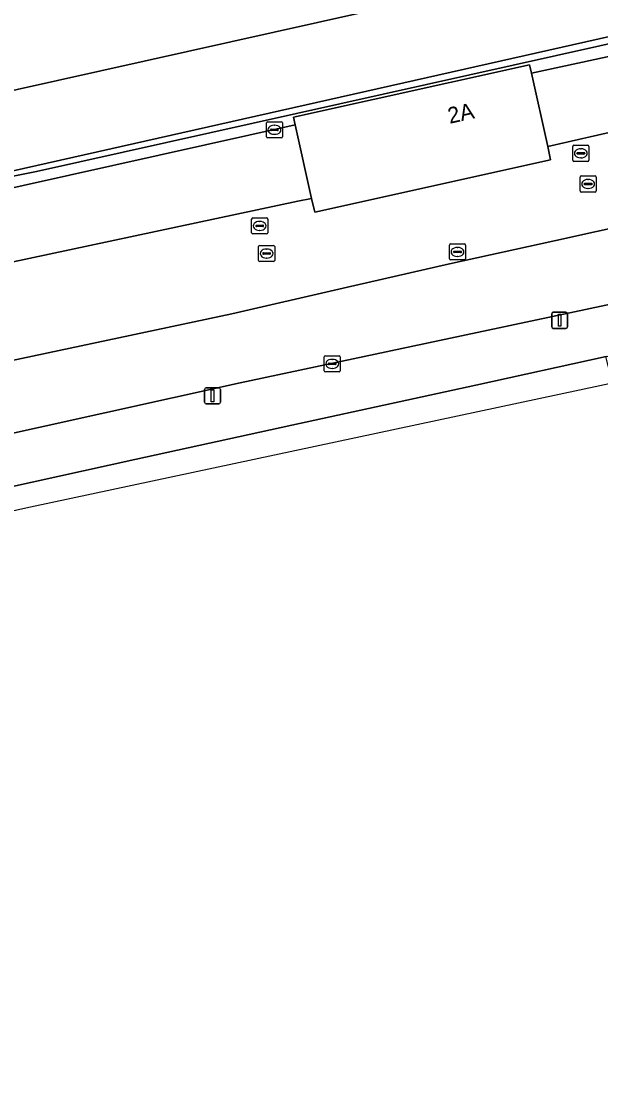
# Model space of a CAD drawing. Extents: x 160806 to 161707, y 383696 to 384148.
# Drawn here: x 161634.3 to 161670.2, y 383820.6 to 383887.5 of the extents above; entities that cross this region are included whole.
import ezdxf

# ---------------------------------------------------------------- set-up
doc = ezdxf.new("R2010")
doc.units = 0
for name, color, linetype in [('IMGEO_Grasland_overig', 7, 'Continuous'), ('IMGEO_Groenvoorziening', 7, 'Continuous'), ('IMGEO_Hek', 7, 'Continuous'), ('IMGEO_Kolk', 7, 'Continuous'), ('IMGEO_Lichtmast', 7, 'Continuous'), ('IMGEO_Pand', 7, 'Continuous'), ('IMGEO_Pand_nummerreeks', 7, 'Continuous'), ('IMGEO_Parkeervlak_open', 7, 'Continuous'), ('IMGEO_Rijbaan_lokaal_open', 7, 'Continuous'), ('IMGEO_Rioolput', 7, 'Continuous'), ('IMGEO_Spoorbaan_halfverhard', 7, 'Continuous')]:
    doc.layers.add(name, color=color, linetype=linetype)

msp = doc.modelspace()

# ---------------------------------------------------------------- linework, layer by layer
at = {"layer": 'IMGEO_Grasland_overig'}
msp.add_lwpolyline([(161630.532, 383877.228), (161635.195, 383878.161), (161675.596, 383887.152), (161680.158, 383888.167), (161679.423, 383891.492), (161674.766, 383890.452), (161675.408, 383887.573), (161606.306, 383872.021), (161606.363, 383871.769)], close=True, dxfattribs=at)
at = {"layer": 'IMGEO_Groenvoorziening'}
for points in [[(161675.596, 383887.152), (161635.195, 383878.161), (161630.532, 383877.228), (161606.363, 383871.769), (161606.519, 383871.073), (161626.185, 383875.445), (161628.76, 383876.043), (161651.274, 383881.048), (161651.168, 383881.526), (161665.845, 383884.775), (161665.96, 383884.257), (161675.376, 383886.281)], [(161521.635, 383833.723), (161580.201, 383846.689), (161582.51, 383847.687), (161585.012, 383847.75), (161614.342, 383854.325), (161641.301, 383860.274), (161651.06, 383862.411), (161662.497, 383864.892), (161670.593, 383866.669), (161682.93, 383869.376), (161687.731, 383870.454), (161692.46, 383871.911), (161696.167, 383872.737), (161692.17, 383874.476), (161678.693, 383871.571), (161647.839, 383865.039), (161626.972, 383860.422), (161609.694, 383856.527), (161595.494, 383853.326)]]:
    msp.add_lwpolyline(points, dxfattribs=at)
at = {"layer": 'IMGEO_Hek'}
for points in [[(161679.423, 383891.492), (161674.766, 383890.452), (161675.408, 383887.573), (161592.484, 383868.91)], [(161468.352, 383821.972), (161470.021, 383822.345), (161472.634, 383822.879), (161475.023, 383823.371), (161479.934, 383824.467), (161509.272, 383830.942), (161514.217, 383832.035), (161521.635, 383833.723), (161580.201, 383846.689), (161582.51, 383847.687), (161585.012, 383847.75), (161614.342, 383854.325), (161641.301, 383860.274), (161651.06, 383862.411), (161662.497, 383864.892), (161670.593, 383866.669), (161682.93, 383869.376), (161687.731, 383870.454), (161692.46, 383871.911), (161696.167, 383872.737)]]:
    msp.add_lwpolyline(points, dxfattribs=at)
at = {"layer": 'IMGEO_Kolk'}
for p, q in [((161649.554, 383881.243), (161650.406, 383881.243)), ((161649.479, 383880.317), (161649.479, 383881.169)), ((161649.738, 383880.737), (161649.738, 383880.749)), ((161650.176, 383880.7), (161649.778, 383880.7)), ((161649.781, 383880.786), (161650.179, 383880.786)), ((161649.967, 383881.023), (161649.992, 383881.023)), ((161650.222, 383880.749), (161650.222, 383880.737)), ((161650.48, 383881.169), (161650.48, 383880.317)), ((161650.406, 383880.243), (161649.554, 383880.243)), ((161649.99, 383880.463), (161649.965, 383880.463)), ((161660.86, 383872.734), (161660.86, 383873.586)), ((161660.935, 383873.66), (161661.787, 383873.66)), ((161661.348, 383873.44), (161661.373, 383873.44)), ((161661.861, 383873.586), (161661.861, 383872.734)), ((161661.787, 383872.66), (161660.935, 383872.66)), ((161661.119, 383873.154), (161661.119, 383873.166)), ((161661.557, 383873.117), (161661.159, 383873.117)), ((161661.162, 383873.203), (161661.56, 383873.203)), ((161661.371, 383872.88), (161661.346, 383872.88)), ((161661.603, 383873.166), (161661.603, 383873.154)), ((161653.073, 383865.783), (161653.073, 383866.635)), ((161653.148, 383866.709), (161654, 383866.709)), ((161654.074, 383866.635), (161654.074, 383865.783)), ((161653.332, 383866.203), (161653.332, 383866.215)), ((161653.77, 383866.166), (161653.372, 383866.166)), ((161653.375, 383866.252), (161653.773, 383866.252)), ((161653.584, 383865.929), (161653.559, 383865.929)), ((161653.561, 383866.489), (161653.586, 383866.489)), ((161653.816, 383866.215), (161653.816, 383866.203)), ((161654, 383865.709), (161653.148, 383865.709))]:
    msp.add_line(p, q, dxfattribs=at)
for points in [[(161649.554, 383881.243), (161650.406, 383881.243)], [(161649.479, 383880.317), (161649.479, 383881.169)], [(161650.48, 383881.169), (161650.48, 383880.317)], [(161650.406, 383880.243), (161649.554, 383880.243)], [(161660.86, 383872.734), (161660.86, 383873.586)], [(161660.935, 383873.66), (161661.787, 383873.66)], [(161661.861, 383873.586), (161661.861, 383872.734)], [(161661.787, 383872.66), (161660.935, 383872.66)], [(161653.073, 383865.783), (161653.073, 383866.635)], [(161653.148, 383866.709), (161654, 383866.709)], [(161654.074, 383866.635), (161654.074, 383865.783)], [(161654, 383865.709), (161653.148, 383865.709)]]:
    msp.add_lwpolyline(points, dxfattribs=at)
for centre, radius, start, end in [((161649.556, 383881.167), 0.0765, 91.55205, 178.44795), ((161649.556, 383881.167), 0.0765, 91.55205, 178.44795), ((161650.404, 383881.167), 0.0765, 1.55205, 88.44795), ((161650.404, 383881.167), 0.0765, 1.55205, 88.44795), ((161649.778, 383880.746), 0.0403, 85.87752, 175.75265), ((161649.775, 383880.736), 0.0366, 178.93798, 274.71019), ((161650.179, 383880.743), 0.043, 264.86636, 352.45326), ((161650.183, 383880.748), 0.0386, 1.73085, 96.63898), ((161649.556, 383880.319), 0.0765, 181.55205, 268.44795), ((161649.556, 383880.319), 0.0765, 181.55205, 268.44795), ((161650.404, 383880.319), 0.0765, 271.55205, 358.44795), ((161650.404, 383880.319), 0.0765, 271.55205, 358.44795), ((161660.937, 383873.584), 0.0765, 91.55205, 178.44795), ((161660.937, 383873.584), 0.0765, 91.55205, 178.44795), ((161661.785, 383873.584), 0.0765, 1.55205, 88.44795), ((161661.785, 383873.584), 0.0765, 1.55205, 88.44795), ((161660.937, 383872.736), 0.0765, 181.55205, 268.44795), ((161660.937, 383872.736), 0.0765, 181.55205, 268.44795), ((161661.159, 383873.163), 0.0403, 85.87752, 175.75265), ((161661.156, 383873.153), 0.0366, 178.93798, 274.71019), ((161661.56, 383873.16), 0.043, 264.86636, 352.45326), ((161661.564, 383873.165), 0.0386, 1.73085, 96.63898), ((161661.785, 383872.736), 0.0765, 271.55205, 358.44795), ((161661.785, 383872.736), 0.0765, 271.55205, 358.44795), ((161653.15, 383866.633), 0.0765, 91.55205, 178.44795), ((161653.15, 383866.633), 0.0765, 91.55205, 178.44795), ((161653.998, 383866.633), 0.0765, 1.55205, 88.44795), ((161653.998, 383866.633), 0.0765, 1.55205, 88.44795), ((161653.372, 383866.212), 0.0403, 85.87752, 175.75265), ((161653.369, 383866.202), 0.0366, 178.93798, 274.71019), ((161653.773, 383866.209), 0.043, 264.86636, 352.45326), ((161653.777, 383866.214), 0.0386, 1.73085, 96.63898), ((161653.15, 383865.785), 0.0765, 181.55205, 268.44795), ((161653.15, 383865.785), 0.0765, 181.55205, 268.44795), ((161653.998, 383865.785), 0.0765, 271.55205, 358.44795), ((161653.998, 383865.785), 0.0765, 271.55205, 358.44795)]:
    msp.add_arc(centre, radius, start, end, dxfattribs=at)
for centre, major_axis, ratio, start_param, end_param in [((161649.966, 383880.743), (-0.387, 0.002), 0.722429, 4.712389, 7.853982), ((161649.991, 383880.743), (-0.39, 0.002), 0.717154, 1.570796, 4.712389), ((161661.347, 383873.16), (-0.387, 0.002), 0.722429, 4.712389, 7.853982), ((161661.372, 383873.16), (-0.39, 0.002), 0.717154, 1.570796, 4.712389), ((161653.56, 383866.209), (-0.387, 0.002), 0.722429, 4.712389, 7.853982), ((161653.585, 383866.209), (-0.39, 0.002), 0.717154, 1.570796, 4.712389)]:
    msp.add_ellipse(centre, major_axis=major_axis, ratio=ratio, start_param=start_param, end_param=end_param, dxfattribs=at)
at = {"layer": 'IMGEO_Lichtmast'}
for p, q in [((161667.214, 383868.514), (161667.214, 383869.314)), ((161667.214, 383869.314), (161667.214, 383868.514)), ((161667.314, 383869.414), (161668.104, 383869.414)), ((161668.104, 383869.414), (161667.314, 383869.414)), ((161668.204, 383869.314), (161668.204, 383868.514)), ((161668.204, 383868.514), (161668.204, 383869.314)), ((161668.104, 383868.414), (161667.314, 383868.414)), ((161667.314, 383868.414), (161668.104, 383868.414)), ((161645.634, 383863.819), (161645.634, 383864.619)), ((161645.634, 383864.619), (161645.634, 383863.819)), ((161645.734, 383864.719), (161646.524, 383864.719)), ((161646.524, 383864.719), (161645.734, 383864.719)), ((161646.624, 383864.619), (161646.624, 383863.819)), ((161646.624, 383863.819), (161646.624, 383864.619)), ((161646.524, 383863.719), (161645.734, 383863.719)), ((161645.734, 383863.719), (161646.524, 383863.719))]:
    msp.add_line(p, q, dxfattribs=at)
for points in [[(161667.634, 383869.289), (161667.784, 383869.289), (161667.784, 383868.539), (161667.634, 383868.539), (161667.634, 383869.289)], [(161646.054, 383864.594), (161646.204, 383864.594), (161646.204, 383863.844), (161646.054, 383863.844), (161646.054, 383864.594)]]:
    msp.add_lwpolyline(points, dxfattribs=at)
for centre, start, end in [((161667.314, 383869.314), 90, 180), ((161667.314, 383869.314), 90, 180), ((161668.104, 383869.314), 0, 90), ((161668.104, 383869.314), 360, 90), ((161667.314, 383868.514), 180, 270), ((161667.314, 383868.514), 180, 270), ((161668.104, 383868.514), 270, 0), ((161668.104, 383868.514), 270, 0), ((161645.734, 383864.619), 90, 180), ((161645.734, 383864.619), 90, 180), ((161646.524, 383864.619), 0, 90), ((161646.524, 383864.619), 360, 90), ((161645.734, 383863.819), 180, 270), ((161645.734, 383863.819), 180, 270), ((161646.524, 383863.819), 270, 0), ((161646.524, 383863.819), 270, 0)]:
    msp.add_arc(centre, 0.1, start, end, dxfattribs=at)
at = {"layer": 'IMGEO_Pand'}
msp.add_lwpolyline([(161599.211, 383890.337), (161600.263, 383885.614), (161600.427, 383884.879), (161600.036, 383884.793), (161601.34, 383878.893), (161601.233, 383878.87), (161601.845, 383876.066), (161608.382, 383877.494), (161614.002, 383878.754), (161614.09, 383878.359), (161623.29, 383880.412), (161623.195, 383880.838), (161668.642, 383890.98)], dxfattribs=at)
msp.add_lwpolyline([(161665.96, 383884.257), (161665.845, 383884.775), (161651.168, 383881.526), (161651.274, 383881.048), (161652.29, 383876.485), (161652.481, 383875.629), (161667.151, 383878.878), (161666.967, 383879.708)], close=True, dxfattribs=at)
at = {"layer": 'IMGEO_Parkeervlak_open'}
msp.add_lwpolyline([(161675.855, 383885.976), (161675.673, 383886.219), (161675.376, 383886.281), (161665.96, 383884.257), (161666.967, 383879.708), (161671.512, 383880.738), (161674.153, 383881.35), (161676.735, 383881.898)], close=True, dxfattribs=at)
for points in [[(161651.442, 383876.303), (161652.29, 383876.485), (161651.274, 383881.048), (161628.76, 383876.043), (161626.185, 383875.445), (161606.519, 383871.073), (161591.712, 383867.718), (161592.392, 383864.683)], [(161591.531, 383863.209), (161603.52, 383865.895), (161606.493, 383866.529), (161606.594, 383866.552), (161629.63, 383871.673), (161651.442, 383876.303)], [(161678.693, 383871.571), (161678.868, 383871.878), (161678.822, 383872.229), (161677.981, 383876.124), (161676.579, 383875.892), (161672.537, 383874.994), (161667.473, 383873.86), (161660.853, 383872.411), (161654.242, 383870.901), (161647.339, 383869.306), (161629.555, 383865.552), (161607.736, 383860.676), (161592.972, 383857.432)], [(161595.494, 383853.326), (161609.694, 383856.527), (161626.972, 383860.422), (161647.839, 383865.039), (161678.693, 383871.571)]]:
    msp.add_lwpolyline(points, dxfattribs=at)
at = {"layer": 'IMGEO_Rijbaan_lokaal_open'}
for points in [[(161577.815, 383899.062), (161582.551, 383877.576), (161584.858, 383867.183), (161586.124, 383867.469), (161592.484, 383868.91), (161594.78, 383869.427), (161599.71, 383870.536), (161606.306, 383872.021), (161675.408, 383887.573)], [(161668.642, 383890.98), (161623.195, 383880.838), (161623.29, 383880.412), (161614.09, 383878.359)], [(161654.242, 383870.901), (161660.853, 383872.411), (161667.473, 383873.86), (161672.537, 383874.994), (161676.579, 383875.892), (161677.981, 383876.124), (161676.735, 383881.898), (161674.153, 383881.35), (161671.512, 383880.738), (161666.967, 383879.708), (161667.151, 383878.878), (161652.481, 383875.629), (161652.29, 383876.485), (161651.442, 383876.303), (161629.63, 383871.673), (161606.594, 383866.552), (161606.493, 383866.529), (161603.52, 383865.895), (161591.531, 383863.209), (161590.177, 383862.905)], [(161586.533, 383865.472), (161586.124, 383867.469), (161584.858, 383867.183), (161587.153, 383856.14), (161589.726, 383856.719), (161592.972, 383857.432), (161607.736, 383860.676), (161629.555, 383865.552), (161647.339, 383869.306), (161654.242, 383870.901)]]:
    msp.add_lwpolyline(points, dxfattribs=at)
at = {"layer": 'IMGEO_Rioolput'}
for p, q in [((161668.527, 383878.858), (161668.527, 383879.71)), ((161668.602, 383879.784), (161669.454, 383879.784)), ((161668.786, 383879.278), (161668.786, 383879.29)), ((161669.224, 383879.241), (161668.826, 383879.241)), ((161668.829, 383879.327), (161669.227, 383879.327)), ((161669.015, 383879.564), (161669.04, 383879.564)), ((161669.27, 383879.29), (161669.27, 383879.278)), ((161669.528, 383879.71), (161669.528, 383878.858)), ((161669.454, 383878.784), (161668.602, 383878.784)), ((161669.038, 383879.004), (161669.013, 383879.004)), ((161668.981, 383876.954), (161668.981, 383877.806)), ((161669.056, 383877.88), (161669.908, 383877.88)), ((161669.24, 383877.374), (161669.24, 383877.386)), ((161669.678, 383877.337), (161669.28, 383877.337)), ((161669.283, 383877.423), (161669.681, 383877.423)), ((161669.469, 383877.66), (161669.494, 383877.66)), ((161669.724, 383877.386), (161669.724, 383877.374)), ((161669.982, 383877.806), (161669.982, 383876.954)), ((161669.908, 383876.88), (161669.056, 383876.88)), ((161669.492, 383877.1), (161669.467, 383877.1)), ((161648.638, 383875.277), (161649.49, 383875.277)), ((161648.563, 383874.351), (161648.563, 383875.203)), ((161648.822, 383874.771), (161648.822, 383874.783)), ((161649.26, 383874.734), (161648.862, 383874.734)), ((161648.865, 383874.82), (161649.263, 383874.82)), ((161649.051, 383875.057), (161649.076, 383875.057)), ((161649.306, 383874.783), (161649.306, 383874.771)), ((161649.564, 383875.203), (161649.564, 383874.351)), ((161649.49, 383874.277), (161648.638, 383874.277)), ((161649.074, 383874.497), (161649.049, 383874.497)), ((161648.993, 383872.635), (161648.993, 383873.487)), ((161649.068, 383873.561), (161649.92, 383873.561)), ((161649.481, 383873.341), (161649.506, 383873.341)), ((161649.994, 383873.487), (161649.994, 383872.635)), ((161649.92, 383872.561), (161649.068, 383872.561)), ((161649.252, 383873.055), (161649.252, 383873.067)), ((161649.69, 383873.018), (161649.292, 383873.018)), ((161649.295, 383873.104), (161649.693, 383873.104)), ((161649.504, 383872.781), (161649.479, 383872.781)), ((161649.736, 383873.067), (161649.736, 383873.055))]:
    msp.add_line(p, q, dxfattribs=at)
for points in [[(161668.527, 383878.858), (161668.527, 383879.71)], [(161668.602, 383879.784), (161669.454, 383879.784)], [(161669.528, 383879.71), (161669.528, 383878.858)], [(161669.454, 383878.784), (161668.602, 383878.784)], [(161668.981, 383876.954), (161668.981, 383877.806)], [(161669.056, 383877.88), (161669.908, 383877.88)], [(161669.982, 383877.806), (161669.982, 383876.954)], [(161669.908, 383876.88), (161669.056, 383876.88)], [(161648.638, 383875.277), (161649.49, 383875.277)], [(161648.563, 383874.351), (161648.563, 383875.203)], [(161649.564, 383875.203), (161649.564, 383874.351)], [(161649.49, 383874.277), (161648.638, 383874.277)], [(161648.993, 383872.635), (161648.993, 383873.487)], [(161649.068, 383873.561), (161649.92, 383873.561)], [(161649.994, 383873.487), (161649.994, 383872.635)], [(161649.92, 383872.561), (161649.068, 383872.561)]]:
    msp.add_lwpolyline(points, dxfattribs=at)
for centre, radius, start, end in [((161668.604, 383879.708), 0.0765, 91.55205, 178.44795), ((161668.604, 383879.708), 0.0765, 91.55205, 178.44795), ((161668.826, 383879.287), 0.0403, 85.87752, 175.75265), ((161668.823, 383879.277), 0.0366, 178.93798, 274.71019), ((161669.227, 383879.284), 0.043, 264.86636, 352.45326), ((161669.231, 383879.289), 0.0386, 1.73085, 96.63898), ((161669.452, 383879.708), 0.0765, 1.55205, 88.44795), ((161669.452, 383879.708), 0.0765, 1.55205, 88.44795), ((161668.604, 383878.86), 0.0765, 181.55205, 268.44795), ((161668.604, 383878.86), 0.0765, 181.55205, 268.44795), ((161669.452, 383878.86), 0.0765, 271.55205, 358.44795), ((161669.452, 383878.86), 0.0765, 271.55205, 358.44795), ((161669.058, 383877.804), 0.0765, 91.55205, 178.44795), ((161669.058, 383877.804), 0.0765, 91.55205, 178.44795), ((161669.28, 383877.383), 0.0403, 85.87752, 175.75265), ((161669.277, 383877.373), 0.0366, 178.93798, 274.71019), ((161669.681, 383877.38), 0.043, 264.86636, 352.45326), ((161669.685, 383877.385), 0.0386, 1.73085, 96.63898), ((161669.906, 383877.804), 0.0765, 1.55205, 88.44795), ((161669.906, 383877.804), 0.0765, 1.55205, 88.44795), ((161669.058, 383876.956), 0.0765, 181.55205, 268.44795), ((161669.058, 383876.956), 0.0765, 181.55205, 268.44795), ((161669.906, 383876.956), 0.0765, 271.55205, 358.44795), ((161669.906, 383876.956), 0.0765, 271.55205, 358.44795), ((161648.64, 383875.201), 0.0765, 91.55205, 178.44795), ((161648.64, 383875.201), 0.0765, 91.55205, 178.44795), ((161649.488, 383875.201), 0.0765, 1.55205, 88.44795), ((161649.488, 383875.201), 0.0765, 1.55205, 88.44795), ((161648.862, 383874.78), 0.0403, 85.87752, 175.75265), ((161648.859, 383874.77), 0.0366, 178.93798, 274.71019), ((161649.263, 383874.777), 0.043, 264.86636, 352.45326), ((161649.267, 383874.782), 0.0386, 1.73085, 96.63898), ((161648.64, 383874.353), 0.0765, 181.55205, 268.44795), ((161648.64, 383874.353), 0.0765, 181.55205, 268.44795), ((161649.488, 383874.353), 0.0765, 271.55205, 358.44795), ((161649.488, 383874.353), 0.0765, 271.55205, 358.44795), ((161649.07, 383873.485), 0.0765, 91.55205, 178.44795), ((161649.07, 383873.485), 0.0765, 91.55205, 178.44795), ((161649.918, 383873.485), 0.0765, 1.55205, 88.44795), ((161649.918, 383873.485), 0.0765, 1.55205, 88.44795), ((161649.07, 383872.637), 0.0765, 181.55205, 268.44795), ((161649.07, 383872.637), 0.0765, 181.55205, 268.44795), ((161649.292, 383873.064), 0.0403, 85.87752, 175.75265), ((161649.289, 383873.054), 0.0366, 178.93798, 274.71019), ((161649.693, 383873.061), 0.043, 264.86636, 352.45326), ((161649.697, 383873.066), 0.0386, 1.73085, 96.63898), ((161649.918, 383872.637), 0.0765, 271.55205, 358.44795), ((161649.918, 383872.637), 0.0765, 271.55205, 358.44795)]:
    msp.add_arc(centre, radius, start, end, dxfattribs=at)
for centre, major_axis, ratio, start_param, end_param in [((161669.014, 383879.284), (-0.387, 0.002), 0.722429, 4.712389, 7.853982), ((161669.039, 383879.284), (-0.39, 0.002), 0.717154, 1.570796, 4.712389), ((161669.468, 383877.38), (-0.387, 0.002), 0.722429, 4.712389, 7.853982), ((161669.493, 383877.38), (-0.39, 0.002), 0.717154, 1.570796, 4.712389), ((161649.05, 383874.777), (-0.387, 0.002), 0.722429, 4.712389, 7.853982), ((161649.075, 383874.777), (-0.39, 0.002), 0.717154, 1.570796, 4.712389), ((161649.48, 383873.061), (-0.387, 0.002), 0.722429, 4.712389, 7.853982), ((161649.505, 383873.061), (-0.39, 0.002), 0.717154, 1.570796, 4.712389)]:
    msp.add_ellipse(centre, major_axis=major_axis, ratio=ratio, start_param=start_param, end_param=end_param, dxfattribs=at)
at = {"layer": 'IMGEO_Spoorbaan_halfverhard'}
msp.add_lwpolyline([(161469.119, 383820.647), (161634.815, 383857.326), (161692.966, 383869.711), (161692.928, 383869.885), (161693.041, 383869.91), (161693.023, 383869.99), (161692.62, 383870.112), (161688.454, 383869.869), (161670.738, 383866.006), (161670.61, 383866.592), (161670.593, 383866.669), (161662.497, 383864.892), (161651.06, 383862.411), (161641.301, 383860.274), (161614.342, 383854.325), (161585.012, 383847.75), (161582.51, 383847.687), (161580.201, 383846.689), (161521.635, 383833.723)], dxfattribs=at)

# ---------------------------------------------------------------- texts
at = {"layer": 'IMGEO_Pand_nummerreeks'}
msp.add_text('2A', height=1, rotation=12.48475, dxfattribs=at).set_placement((161660.874, 383881.114))

doc.saveas('drawing.dxf')
